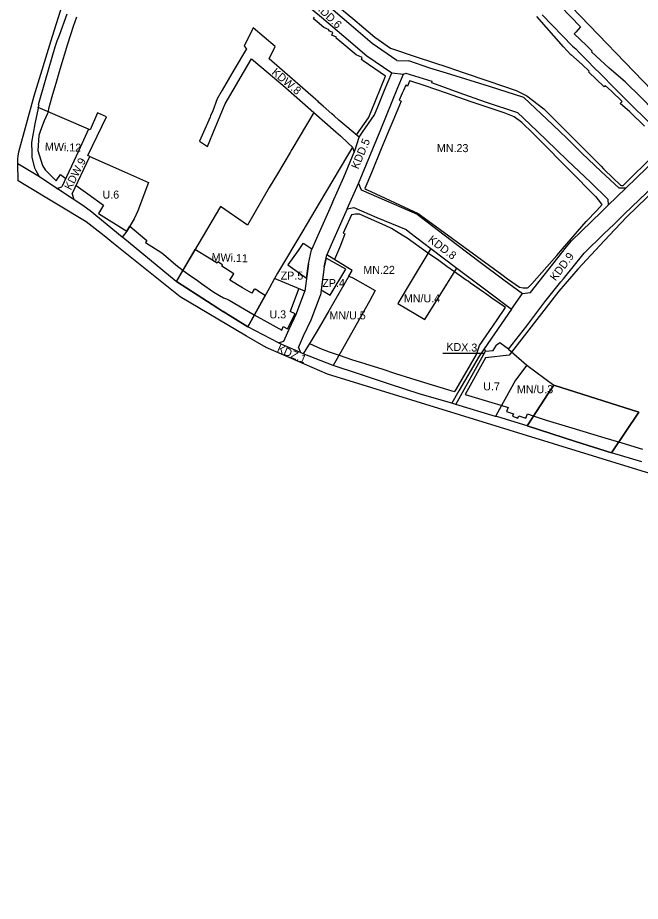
# Model space of a CAD drawing. Extents: x 7418991 to 7423142, y 5547704 to 5549547.
# Drawn here: x 7419403 to 7419792, y 5547967 to 5548519 of the extents above; entities that cross this region are included whole.
import ezdxf

# ---------------------------------------------------------------- set-up
doc = ezdxf.new("R2010")
doc.units = 0
for name, color, linetype in [('LIN_Linia Zabudowy Nieprzekraczalna', 7, 'Continuous'), ('LIN_linie_rozgraniczajace', 7, 'Continuous'), ('strefa_lokalizacji_usług', 7, 'Continuous'), ('TRS_Strefa dopuszczonej lokalizacji miejsc do parkowania', 7, 'Continuous'), ('TXT_Oznaczenia_przeznaczen', 7, 'Continuous')]:
    doc.layers.add(name, color=color, linetype=linetype)

msp = doc.modelspace()

# ---------------------------------------------------------------- linework, layer by layer
at = {"layer": 'LIN_Linia Zabudowy Nieprzekraczalna'}
for p, q in [((7419717.86, 5548558.33), (7419819.96, 5548451.81)), ((7419647.92, 5548479.33), (7419646.61, 5548476.17)), ((7419568.13, 5548323.76), (7419569.09, 5548325.93)), ((7419710.14, 5548308.14), (7419695.46, 5548306.51)), ((7419695.46, 5548306.51), (7419682.63, 5548283.48))]:
    msp.add_line(p, q, dxfattribs=at)
for points in [[(7419598.69, 5548530.09), (7419612.57, 5548518.33), (7419626.37, 5548506.65), (7419635.96, 5548499.9), (7419652.73, 5548494.28), (7419671.85, 5548487.87), (7419681.46, 5548484.65), (7419696.87, 5548479.52), (7419714.47, 5548473.35), (7419721.16, 5548470.17), (7419731.84, 5548461.97), (7419736.41, 5548457.42), (7419739.03, 5548454.67), (7419748.35, 5548445.34), (7419754.89, 5548438.75), (7419755.66, 5548437.97), (7419757.36, 5548436.27), (7419767.51, 5548426.13), (7419768.97, 5548424.51), (7419769.67, 5548423.75), (7419779.66, 5548414.28), (7419780.2, 5548414.14), (7419781.29, 5548414.06), (7419781.33, 5548414.06), (7419801.15, 5548433.63)], [(7419440, 5548519.24), (7419438.02, 5548513.34), (7419434.35, 5548502.37), (7419429.5, 5548486.5), (7419427.44, 5548479.31), (7419424.7, 5548469.53), (7419422.61, 5548461.98), (7419422.26, 5548460.67), (7419421.81, 5548458.96), (7419419.92, 5548454.52), (7419417.54, 5548448.35), (7419416.55, 5548445.33), (7419415.89, 5548435.86), (7419418.75, 5548426.52), (7419420.41, 5548423.77), (7419422.95, 5548421.25), (7419427.29, 5548416.9), (7419430.04, 5548420.87), (7419430.04, 5548420.87), (7419433.35, 5548418.54)], [(7419614.9, 5548445.62), (7419622.25, 5548456.35), (7419623.89, 5548460.28), (7419632.84, 5548482.34), (7419618.94, 5548491.9), (7419617.86, 5548492.83), (7419618.37, 5548493.98), (7419614.57, 5548495.63), (7419604.42, 5548504.27), (7419602.18, 5548506.17), (7419602.37, 5548506.61), (7419599.33, 5548507.98), (7419600.08, 5548509.61), (7419597.59, 5548510.75), (7419597.84, 5548511.25), (7419594.39, 5548512.77), (7419590.32, 5548516.23), (7419588.03, 5548518.15), (7419588.53, 5548519.17)], [(7419794.66, 5548451.16), (7419785.41, 5548460.15), (7419779.41, 5548465.29), (7419780.65, 5548466.62), (7419774.01, 5548472.89), (7419770.16, 5548476.5), (7419769.38, 5548475.68), (7419759.6, 5548484.98), (7419760.12, 5548485.55), (7419755.8, 5548489.62), (7419748.7, 5548495.9), (7419748.56, 5548495.74), (7419744.03, 5548500.72), (7419727.35, 5548519.57)], [(7419657.68, 5548476.24), (7419648.15, 5548479.46), (7419647.92, 5548479.33)], [(7419646.61, 5548476.17), (7419645.54, 5548476.63), (7419644.15, 5548473.42), (7419643.37, 5548471.63), (7419641.53, 5548467.35), (7419642.74, 5548466.83)], [(7419706.94, 5548459.37), (7419699.53, 5548461.86), (7419686.5, 5548466.33), (7419670.99, 5548471.71), (7419657.66, 5548476.25)], [(7419642.74, 5548466.83), (7419637.5, 5548454.17), (7419634.45, 5548446.9), (7419630.19, 5548436.99), (7419624.18, 5548422.08), (7419620.02, 5548412.27)], [(7419760.24, 5548410.99), (7419751.58, 5548419.95), (7419724.99, 5548446.78), (7419718.05, 5548453.42), (7419713.27, 5548456.87), (7419706.94, 5548459.37)], [(7419816.95, 5548426.47), (7419808.61, 5548418.6), (7419797.18, 5548407.61), (7419796, 5548406.59), (7419783.69, 5548394.56), (7419776.16, 5548386.69), (7419769.62, 5548379.68), (7419753.04, 5548361.82), (7419741.07, 5548348.15), (7419710.14, 5548308.14)], [(7419439.71, 5548414.07), (7419447.13, 5548408.85), (7419456.92, 5548401.7)], [(7419620.02, 5548412.27), (7419620.64, 5548411.81), (7419621.14, 5548411.57), (7419653.29, 5548396.55)], [(7419768.12, 5548402.14), (7419767.8, 5548402.64), (7419766.71, 5548404.03), (7419765.86, 5548405.13), (7419764.46, 5548406.93), (7419764.11, 5548407.27), (7419760.24, 5548410.99)], [(7419456.92, 5548401.7), (7419453.76, 5548396.54), (7419471.52, 5548385.53), (7419473.32, 5548388.77)], [(7419721.59, 5548350.24), (7419721.99, 5548350.38), (7419724.37, 5548352.64), (7419739.81, 5548370.33), (7419743.43, 5548374.47), (7419758.32, 5548391.49), (7419764.87, 5548398.47), (7419768.12, 5548402.14)], [(7419611.67, 5548395.78), (7419607.4, 5548386.26), (7419606.6, 5548384.26), (7419607.6, 5548383.8)], [(7419632.68, 5548389.17), (7419620.37, 5548394.54), (7419616.61, 5548396.18), (7419614.17, 5548396.21), (7419611.67, 5548395.78)], [(7419653.29, 5548396.55), (7419659.28, 5548392.24), (7419705.54, 5548358.42), (7419709.17, 5548355.85), (7419716.57, 5548350.63), (7419718.85, 5548350.07), (7419721.59, 5548350.24)], [(7419473.32, 5548388.77), (7419482.67, 5548380.76), (7419483.92, 5548379.74)], [(7419694.05, 5548347.49), (7419686.06, 5548353.17), (7419684.47, 5548354.27), (7419683.33, 5548355.03), (7419675.95, 5548360.25), (7419671.23, 5548363.49), (7419666.17, 5548367.17), (7419659.23, 5548372.08), (7419646.55, 5548381.13), (7419643.4, 5548383.02), (7419636.7, 5548387.19), (7419632.68, 5548389.17)], [(7419483.92, 5548379.74), (7419483.11, 5548378.42), (7419489.23, 5548374.59), (7419492.56, 5548372.51)], [(7419607.6, 5548383.8), (7419604.8, 5548376.66), (7419601.07, 5548367.79)], [(7419492.56, 5548372.51), (7419494.28, 5548371.15), (7419502.01, 5548364.57), (7419506.6, 5548360.94), (7419511.88, 5548357.13), (7419514.79, 5548355.32), (7419518.09, 5548352.96), (7419525.82, 5548347.46), (7419531.75, 5548343.99), (7419533.66, 5548343.29), (7419535.32, 5548342.38), (7419550.9, 5548333.22)], [(7419573.5, 5548335.37), (7419573.6, 5548335.59), (7419578.81, 5548349.6)], [(7419707.76, 5548337.79), (7419699.35, 5548343.72), (7419695.37, 5548346.55), (7419694.05, 5548347.49)], [(7419569.09, 5548325.93), (7419571.82, 5548324.52), (7419576.45, 5548333.86), (7419573.5, 5548335.37)], [(7419691.66, 5548314.06), (7419695.85, 5548320.24), (7419702.64, 5548330.25), (7419707.76, 5548337.79)], [(7419550.9, 5548333.22), (7419558.81, 5548328.84), (7419568.13, 5548323.76)], [(7419585.54, 5548315.42), (7419592.44, 5548312.32), (7419597.71, 5548310.28), (7419603.95, 5548308), (7419612.38, 5548305.29), (7419619.96, 5548302.93), (7419620.5, 5548302.72), (7419630.55, 5548299.56), (7419639.24, 5548296.75), (7419648.58, 5548293.79), (7419657.3, 5548291.09), (7419671.66, 5548286.66), (7419674.4, 5548285.89), (7419676.2, 5548285.38)], [(7419676.2, 5548285.38), (7419676.96, 5548286.74), (7419689.66, 5548308.51), (7419691.66, 5548314.06)], [(7419682.63, 5548283.48), (7419699.3, 5548278.49), (7419704.86, 5548276.9), (7419709.47, 5548275.42)], [(7419709.47, 5548275.42), (7419708.57, 5548272.97), (7419712.82, 5548271.46), (7419712.32, 5548270.06), (7419715.63, 5548268.86), (7419716.12, 5548270.26), (7419720.49, 5548268.73), (7419721.51, 5548271.48)], [(7419721.51, 5548271.48), (7419724.57, 5548270.33), (7419733.19, 5548267.59), (7419747.21, 5548263.26), (7419762.91, 5548258.58), (7419769.84, 5548256.52), (7419780.42, 5548253.35), (7419793.36, 5548249.33)]]:
    msp.add_lwpolyline(points, dxfattribs=at)
at = {"layer": 'LIN_linie_rozgraniczajace'}
for p, q in [((7419754.71, 5548513.21), (7419751.71, 5548509.79)), ((7419640.05, 5548492.21), (7419647.47, 5548491.9)), ((7419636.83, 5548484.45), (7419644.09, 5548483.65)), ((7419447.6, 5548449.23), (7419416.04, 5548462.78)), ((7419612.34, 5548437.91), (7419613.31, 5548434.84)), ((7419427.71, 5548412.27), (7419430.84, 5548413.15)), ((7419437.25, 5548408.87), (7419438.26, 5548405.22)), ((7419584.8, 5548365.2), (7419586.75, 5548373.86)), ((7419594.64, 5548363.37), (7419596.29, 5548370.71)), ((7419612.19, 5548361.01), (7419596.29, 5548370.71)), ((7419584.8, 5548365.2), (7419582.51, 5548348.06)), ((7419594.64, 5548363.37), (7419592.27, 5548345.62)), ((7419610.05, 5548357.34), (7419612.19, 5548361.01)), ((7419566.2, 5548315.75), (7419569.45, 5548316.9)), ((7419578.64, 5548312.96), (7419579.92, 5548309.7)), ((7419694.55, 5548312.1), (7419695.41, 5548310.53))]:
    msp.add_line(p, q, dxfattribs=at)
for points in [[(7419684.13, 5548570.46), (7419697.75, 5548563.75), (7419712.63, 5548553.29), (7419727.44, 5548540.59), (7419742.18, 5548526.09), (7419754.71, 5548513.21)], [(7419640.05, 5548492.21), (7419624.7, 5548502.82), (7419609.99, 5548515.28), (7419596.11, 5548527.03), (7419582.31, 5548538.67), (7419568.5, 5548550.18), (7419566.25, 5548545.38), (7419562.87, 5548538.52), (7419576.59, 5548526.98), (7419578.67, 5548531.3), (7419592.9, 5548519.28), (7419607.01, 5548507.32), (7419621.38, 5548495.08), (7419636.83, 5548484.45)], [(7420325.12, 5547967), (7420017.42, 5548144.29), (7419955.38, 5548181), (7419929.91, 5548196.08), (7419793.21, 5548235.75), (7419596.81, 5548296.15), (7419558.42, 5548312.8), (7419546.12, 5548320.07), (7419546.12, 5548320.06), (7419504.75, 5548344.51), (7419463.08, 5548377.86), (7419457.25, 5548382.53), (7419446.13, 5548391.44), (7419408.3, 5548414.15), (7419403.6, 5548416.97), (7419403.3, 5548427.68), (7419403.28, 5548428.22), (7419403.44, 5548430.77), (7419403.61, 5548432.44), (7419404.03, 5548435.15), (7419413.56, 5548470.15), (7419425.07, 5548507.35), (7419431.26, 5548527.19)], [(7419416.96, 5548419.46), (7419415.68, 5548421.69), (7419414.91, 5548423.21), (7419414.01, 5548424.97), (7419412.27, 5548431.81), (7419412.24, 5548434.55), (7419412.15, 5548440.89), (7419414.26, 5548452.59), (7419416.38, 5548462.37), (7419416.04, 5548462.78), (7419416.71, 5548464.43), (7419416.35, 5548464.64), (7419420.56, 5548479.82), (7419426.73, 5548500.6), (7419428.02, 5548504.37), (7419429.32, 5548507.99), (7419434.22, 5548521.2)], [(7419730.82, 5548520.64), (7419749.71, 5548501.07), (7419751.69, 5548499.35), (7419754.06, 5548496.96), (7419759.39, 5548491.54), (7419762.83, 5548488.04), (7419767.29, 5548483.57), (7419775.92, 5548474.95), (7419785.15, 5548465.67), (7419797.38, 5548453.56), (7419809.02, 5548441.68), (7419813.1, 5548437.36), (7419820.94, 5548429.57), (7419832.45, 5548417.92), (7419846.22, 5548403.72), (7419864.18, 5548385.61), (7419875.46, 5548373.86), (7419885.22, 5548364.96), (7419895.76, 5548354.52), (7419905.88, 5548343.51), (7419924.62, 5548324.86)], [(7419616.44, 5548444.33), (7419603.89, 5548454.83), (7419600.9, 5548457.49), (7419599.44, 5548458.79), (7419594.03, 5548463.61), (7419591.37, 5548465.98), (7419590.83, 5548466.46), (7419589.84, 5548467.33), (7419589.39, 5548467.74), (7419574.85, 5548480.46), (7419560.22, 5548493.09), (7419563.98, 5548500.97), (7419550.22, 5548512.46), (7419544.62, 5548501.04), (7419546.12, 5548499.46)], [(7419782.56, 5548478.75), (7419772.65, 5548487.3), (7419761.53, 5548497.5), (7419762.01, 5548497.98), (7419758.44, 5548501.44), (7419750.82, 5548508.78), (7419751.71, 5548509.79)], [(7419546.12, 5548499.46), (7419538.54, 5548486.54), (7419530.95, 5548473.62), (7419527.83, 5548468.29), (7419525.14, 5548460.76), (7419523.73, 5548457.5), (7419523.4, 5548456.71), (7419516.8, 5548441.71), (7419521.8, 5548438.39), (7419526.6, 5548450), (7419532.82, 5548465.01), (7419549.32, 5548493.13)], [(7419549.32, 5548493.13), (7419568.77, 5548476.66), (7419588.22, 5548459.65), (7419601.99, 5548447.68), (7419604.77, 5548445.05), (7419609.35, 5548440.72), (7419612.34, 5548437.91)], [(7419783.05, 5548412.46), (7419778.92, 5548412.4), (7419767.69, 5548422.77), (7419755.6, 5548434.18), (7419746.37, 5548443.37), (7419737.43, 5548451.99), (7419719.3, 5548469.13), (7419697.95, 5548475.87), (7419670.97, 5548484.26), (7419660.59, 5548487.45), (7419647.47, 5548491.9)], [(7419609.02, 5548399.41), (7419616.08, 5548415.41), (7419630.02, 5548449.03), (7419640.68, 5548475.24), (7419644.09, 5548483.65)], [(7419618.48, 5548447.31), (7419625.98, 5548458.26), (7419628.46, 5548464.26), (7419632.35, 5548473.64), (7419636.83, 5548484.45)], [(7419644.09, 5548483.65), (7419645.73, 5548484.14), (7419661.88, 5548479.17), (7419661.62, 5548478.33), (7419678.78, 5548472.16), (7419695.21, 5548466.25), (7419715.36, 5548459.67), (7419723.03, 5548452.34), (7419733.28, 5548442.54), (7419746.45, 5548429.79), (7419761.07, 5548415.86), (7419771.78, 5548405.54), (7419771.93, 5548401.71)], [(7419889.76, 5548370.5), (7419882.1, 5548378.06), (7419879.58, 5548380.54), (7419869.45, 5548391), (7419859.11, 5548401.41), (7419838.3, 5548422.48), (7419826.12, 5548434.85), (7419823.92, 5548437.08), (7419818.94, 5548442.13), (7419814.47, 5548446.68), (7419807.54, 5548453.72), (7419792.57, 5548469.04), (7419782.56, 5548478.75)], [(7419453.19, 5548459.5), (7419448.52, 5548448.84), (7419447.6, 5548449.23), (7419441.19, 5548435.43), (7419430.84, 5548413.15)], [(7419437.25, 5548408.87), (7419448.33, 5548432.26), (7419447.18, 5548432.77), (7419458.77, 5548457.05), (7419453.19, 5548459.5)], [(7419588.22, 5548459.65), (7419574.48, 5548436.47), (7419573.46, 5548434.75), (7419565.47, 5548421.33), (7419560.33, 5548412.76), (7419546.82, 5548389.38), (7419529.85, 5548400.88), (7419502.23, 5548354.21)], [(7419599.88, 5548403.46), (7419606.89, 5548419.34), (7419613.31, 5548434.84), (7419613.95, 5548436.39), (7419616.44, 5548444.33), (7419618.48, 5548447.31)], [(7419711.52, 5548336.84), (7419718.53, 5548346.58), (7419723.44, 5548347.14), (7419745.99, 5548375.71), (7419749.05, 5548379.46), (7419767.7, 5548397.59), (7419771.93, 5548401.71), (7419783.05, 5548412.46), (7419809.15, 5548437.71), (7419809.02, 5548441.68)], [(7419612.34, 5548437.91), (7419609.27, 5548432.76), (7419591.58, 5548403.08), (7419581.25, 5548385.77), (7419565.48, 5548359.32), (7419563.61, 5548355.93), (7419560.43, 5548350.18), (7419546.89, 5548325.71)], [(7419448.33, 5548432.26), (7419470.04, 5548422.64), (7419485.02, 5548416), (7419478.34, 5548398.25), (7419476.06, 5548393.24), (7419471.52, 5548385.53), (7419468.62, 5548381.77)], [(7419709.69, 5548311.91), (7419721.08, 5548326.49), (7419732.33, 5548341.35), (7419742.43, 5548353.99), (7419743.97, 5548355.73), (7419756.88, 5548371.75), (7419769.48, 5548384.13), (7419775.41, 5548389.8), (7419782.19, 5548396.29), (7419795.85, 5548409.55), (7419816.87, 5548429.82), (7419820.94, 5548429.57)], [(7419546.89, 5548325.71), (7419531.63, 5548335.3), (7419531.43, 5548335.42), (7419528.24, 5548337.47), (7419502.37, 5548354.1), (7419502.23, 5548354.21), (7419468.97, 5548381.49), (7419468.62, 5548381.77), (7419448.57, 5548398.32), (7419444.74, 5548400.88), (7419438.26, 5548405.22), (7419436.18, 5548406.61), (7419429.79, 5548410.88), (7419427.71, 5548412.27), (7419416.96, 5548419.46), (7419403.3, 5548427.68)], [(7419616.08, 5548415.41), (7419617.69, 5548411.41), (7419633.6, 5548404.42), (7419652.66, 5548396.08), (7419662.43, 5548388.68), (7419677.46, 5548377.18), (7419692, 5548366.09), (7419706.91, 5548355.11), (7419718.53, 5548346.58)], [(7419599.88, 5548403.46), (7419589.9, 5548380.97), (7419586.75, 5548373.86)], [(7419609.02, 5548399.41), (7419599.04, 5548376.92), (7419596.29, 5548370.71)], [(7419609.02, 5548399.41), (7419613.21, 5548400.29), (7419627.48, 5548394.18), (7419645.8, 5548386.51), (7419648.04, 5548384.75), (7419661.17, 5548374.63), (7419677.45, 5548362.42), (7419694.76, 5548349.44), (7419711.52, 5548336.84)], [(7419661.17, 5548374.63), (7419648.98, 5548354.33), (7419640.57, 5548340.32), (7419657.57, 5548330.46), (7419677.45, 5548362.42)], [(7419610.05, 5548357.34), (7419603.73, 5548346.53), (7419597.48, 5548335.86), (7419591.45, 5548325.48), (7419586.51, 5548316.98), (7419581.52, 5548309.01)], [(7419610.05, 5548357.34), (7419612.63, 5548356.36), (7419626.39, 5548348.53), (7419622.94, 5548341.8), (7419605.19, 5548310.33), (7419600.21, 5548301.61)], [(7419582.51, 5548348.06), (7419565.16, 5548355.28), (7419563.61, 5548355.93)], [(7419569.45, 5548316.9), (7419572.74, 5548324.29), (7419577.29, 5548334.04), (7419582.51, 5548348.06)], [(7419578.64, 5548312.96), (7419581.84, 5548320.14), (7419586.52, 5548330.17), (7419592.27, 5548345.62)], [(7419711.52, 5548336.84), (7419694.55, 5548312.1), (7419691.35, 5548307.44), (7419678.7, 5548285.75), (7419674.42, 5548278.06)], [(7419581.52, 5548309.01), (7419579.92, 5548309.7), (7419568.17, 5548314.73), (7419566.2, 5548315.75), (7419546.89, 5548325.71)], [(7419676.9, 5548277.3), (7419695.41, 5548310.53), (7419700.11, 5548311.05), (7419702.22, 5548314.27)], [(7419709.69, 5548311.91), (7419704.33, 5548315.78), (7419702.22, 5548314.27)], [(7419674.42, 5548278.06), (7419654.68, 5548283.79), (7419635.33, 5548289.99), (7419615.98, 5548296.39), (7419600.21, 5548301.61), (7419581.52, 5548309.01)], [(7419709.69, 5548311.91), (7419721.14, 5548301.76), (7419714.16, 5548292.44), (7419704.07, 5548274.43), (7419701.53, 5548269.79)], [(7419721.14, 5548301.76), (7419738.01, 5548289.45)], [(7419721.32, 5548264), (7419724.97, 5548269.37), (7419734.46, 5548284.17), (7419738.01, 5548289.45)], [(7419721.32, 5548264), (7419702.98, 5548269.5), (7419701.53, 5548269.79), (7419676.9, 5548277.3), (7419674.42, 5548278.06)], [(7419793.02, 5548241.57), (7419774.07, 5548247.15), (7419751.56, 5548254.2), (7419721.32, 5548264)]]:
    msp.add_lwpolyline(points, dxfattribs=at)
at = {"layer": 'strefa_lokalizacji_usług'}
for p, q in [((7419513.99, 5548374.09), (7419502.23, 5548354.21)), ((7419546.89, 5548325.71), (7419557.75, 5548345.34)), ((7419734.46, 5548284.17), (7419738.01, 5548289.45)), ((7419738.01, 5548289.45), (7419734.46, 5548284.17)), ((7419738.01, 5548289.45), (7419791.05, 5548272.55)), ((7419791.05, 5548272.55), (7419738.01, 5548289.45)), ((7419724.97, 5548269.37), (7419734.46, 5548284.17)), ((7419734.46, 5548284.17), (7419724.97, 5548269.37)), ((7419721.32, 5548264), (7419724.97, 5548269.37)), ((7419724.97, 5548269.37), (7419721.32, 5548264)), ((7419791.05, 5548272.55), (7419774.07, 5548247.15)), ((7419774.07, 5548247.15), (7419791.05, 5548272.55)), ((7419751.56, 5548254.2), (7419721.32, 5548264)), ((7419721.32, 5548264), (7419751.56, 5548254.2)), ((7419774.07, 5548247.15), (7419751.56, 5548254.2)), ((7419751.56, 5548254.2), (7419774.07, 5548247.15))]:
    msp.add_line(p, q, dxfattribs=at)
for points in [[(7419535.68, 5548354.89), (7419538.21, 5548358.87), (7419530.67, 5548363.67), (7419531.16, 5548364.45), (7419528.3, 5548366.32), (7419527.8, 5548365.55), (7419522.91, 5548368.61), (7419513.99, 5548374.09)], [(7419502.23, 5548354.21), (7419502.37, 5548354.1), (7419528.24, 5548337.47), (7419531.43, 5548335.42), (7419531.63, 5548335.3), (7419546.89, 5548325.71)], [(7419557.75, 5548345.34), (7419553.63, 5548347.81), (7419553.73, 5548347.98), (7419551.49, 5548349.33), (7419551.38, 5548349.14), (7419551.01, 5548349.36), (7419549.49, 5548346.78), (7419543.75, 5548350.14), (7419535.68, 5548354.89)]]:
    msp.add_lwpolyline(points, dxfattribs=at)
at = {"layer": 'TRS_Strefa dopuszczonej lokalizacji miejsc do parkowania'}
for p, q in [((7419578.48, 5548373.42), (7419572.02, 5548364.48)), ((7419581.4, 5548377.8), (7419578.48, 5548373.42)), ((7419581.94, 5548377.62), (7419581.4, 5548377.8)), ((7419586.95, 5548374.32), (7419581.94, 5548377.62)), ((7419584.8, 5548365.2), (7419586.75, 5548373.86)), ((7419586.75, 5548373.86), (7419586.95, 5548374.32)), ((7419595.84, 5548368.73), (7419594.64, 5548363.37)), ((7419608.17, 5548361.73), (7419595.84, 5548368.73)), ((7419572.02, 5548364.48), (7419583.6, 5548356.24)), ((7419583.6, 5548356.24), (7419584.8, 5548365.2)), ((7419594.64, 5548363.37), (7419592.7, 5548348.83)), ((7419598.44, 5548345.53), (7419608.17, 5548361.73)), ((7419592.7, 5548348.83), (7419598.44, 5548345.53))]:
    msp.add_line(p, q, dxfattribs=at)
at = {"layer": 'TXT_Oznaczenia_przeznaczen'}
msp.add_line((7419668.83, 5548309.36), (7419694.36, 5548309.36), dxfattribs=at)

# ---------------------------------------------------------------- texts
for s, rotation, p in [('KDD.6', 316.2383, (7419588.48, 5548525.25)), ('KDW.8', 319.6433, (7419561.48, 5548484.06)), ('MWi.12', 357.9964, (7419420.18, 5548435.95)), ('KDD.5', 67.3486, (7419615.89, 5548423.93)), ('KDW.9', 62.9582, (7419436.54, 5548410.81)), ('KDD.8', 322.9475, (7419659.11, 5548379.33)), ('MWi.11', 357.9964, (7419524.26, 5548366.86)), ('KDD.9', 52.9475, (7419739.12, 5548354.1)), ('KDZ.1', 336.771, (7419564.76, 5548310.36)), ('KDX.3', 358.1681, (7419670.85, 5548310.9))]:
    msp.add_text(s, height=5, rotation=rotation, dxfattribs=at).set_placement(p)
for s, p in [('MN.23', (7419665.02, 5548434.92)), ('U.6', (7419456.24, 5548405.89)), ('MN.22', (7419619.09, 5548358.88)), ('ZP.5', (7419567.46, 5548355.3)), ('ZP.4', (7419593.46, 5548350.65)), ('MN/U.4', (7419644.38, 5548341.1)), ('U.3', (7419560.48, 5548331.08)), ('MN/U.5', (7419597.92, 5548330.46)), ('U.7', (7419693.96, 5548286.12)), ('MN/U.3', (7419714.97, 5548284.35))]:
    msp.add_text(s, height=5, dxfattribs=at).set_placement(p)

doc.saveas('drawing.dxf')
